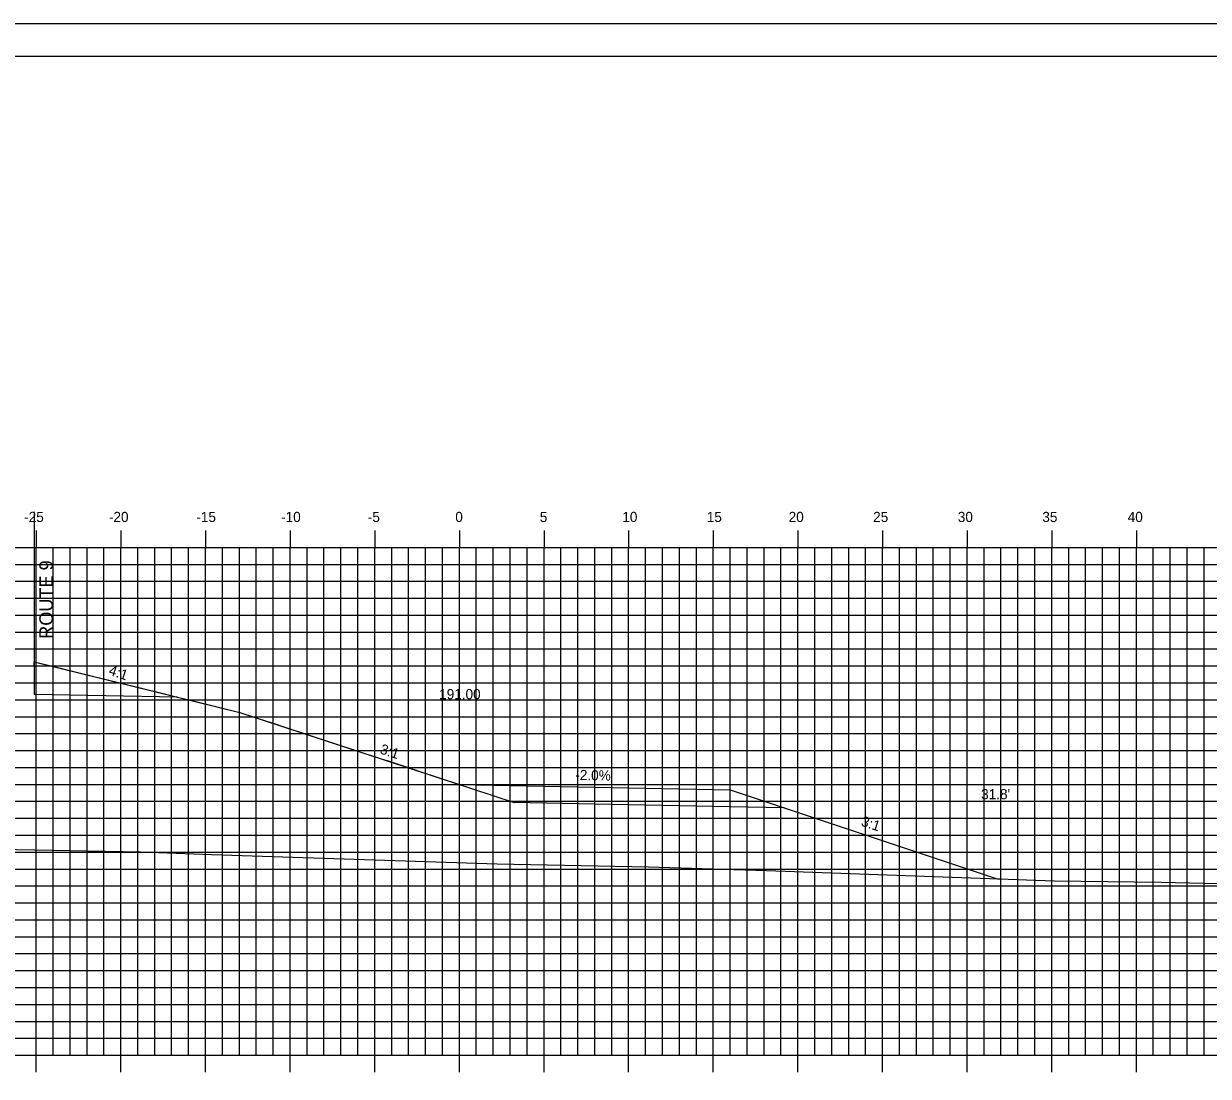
# Model space of a CAD drawing. Extents: x 1723961 to 1724133, y 459560 to 459670.
# Drawn here: x 1724018.7 to 1724088.7, y 459607.4 to 459669.6 of the extents above; entities that cross this region are included whole.
import ezdxf

# ---------------------------------------------------------------- set-up
doc = ezdxf.new("R2010")
doc.units = 0
for name, color, linetype in [('ANNOTATION', 7, 'Continuous'), ('BORDER', 7, 'Continuous'), ('D_Roadway_Centerline', 7, 'Continuous'), ('D_Roadway_Centerline_Text', 7, 'Continuous'), ('D_Roadway_Drive_Gravel', 7, 'Continuous'), ('D_Roadway_Edge_Shoulder', 7, 'Continuous'), ('D_Roadway_SlopeLines', 7, 'Continuous'), ('D_Roadway_SubGrade', 7, 'Continuous'), ('D_Text_Standard', 7, 'Continuous'), ('H_V ANNOTATION', 7, 'Continuous'), ('MAJOR', 7, 'Continuous'), ('MINOR', 7, 'Continuous'), ('PLOT BOUNDARY', 7, 'Continuous'), ('S_Roadway_Centerline', 7, 'Continuous')]:
    doc.layers.add(name, color=color, linetype=linetype)

msp = doc.modelspace()

# ---------------------------------------------------------------- linework, layer by layer
msp.add_lwpolyline([(1724044.473, 459624.613), (1724052.473, 459624.453), (1724060.473, 459624.293), (1724063.665, 459623.229), (1724076.243, 459619.036), (1724076.295, 459619.034), (1724076.313, 459619.033), (1724076.345, 459619.032), (1724076.366, 459619.032), (1724076.395, 459619.031), (1724076.417, 459619.03), (1724076.434, 459619.029)])
at = {"layer": 'BORDER'}
msp.add_lwpolyline([(1723969.473, 459562.613), (1724129.473, 459562.613), (1724129.473, 459667.613), (1723969.473, 459667.613)], close=True, dxfattribs=at)
at = {"layer": 'D_Roadway_Centerline'}
msp.add_lwpolyline([(1724019.359, 459631.855), (1724020.746, 459631.513), (1724022.556, 459631.068), (1724025.54, 459630.335), (1724026.973, 459629.982), (1724027.133, 459629.943), (1724027.825, 459629.773), (1724028.895, 459629.51), (1724031.508, 459628.867), (1724033.199, 459628.312), (1724033.218, 459628.306), (1724033.521, 459628.207), (1724034.108, 459628.014), (1724039.909, 459626.111), (1724040.2, 459626.015), (1724040.858, 459625.799), (1724043.086, 459625.068), (1724044.473, 459624.613)], dxfattribs=at)
at = {"layer": 'D_Roadway_Drive_Gravel'}
msp.add_lwpolyline([(1724044.474, 459624.613), (1724052.473, 459624.453), (1724060.473, 459624.293), (1724063.665, 459623.229), (1724060.473, 459623.293), (1724052.473, 459623.453), (1724047.719, 459623.548)], dxfattribs=at)
at = {"layer": 'D_Roadway_Edge_Shoulder'}
msp.add_line((1724019.359, 459631.855), (1724019.359, 459631.605), dxfattribs=at)
msp.add_line((1724019.359, 459631.855), (1724019.359, 459631.605), dxfattribs=at)
at = {"layer": 'D_Roadway_SlopeLines'}
for points in [[(1724019.359, 459631.855), (1724031.508, 459628.867), (1724047.719, 459623.548)], [(1724019.359, 459631.855), (1724031.508, 459628.867), (1724047.719, 459623.548)], [(1724019.359, 459631.855), (1724031.508, 459628.867), (1724047.719, 459623.548)], [(1724019.359, 459631.855), (1724031.508, 459628.867), (1724047.719, 459623.548)], [(1724019.359, 459631.855), (1724031.508, 459628.867), (1724047.719, 459623.548)], [(1724019.359, 459631.855), (1724031.508, 459628.867), (1724047.719, 459623.548)], [(1724019.359, 459631.855), (1724031.508, 459628.867), (1724044.474, 459624.613)], [(1724060.473, 459624.293), (1724063.665, 459623.229), (1724076.243, 459619.036)]]:
    msp.add_lwpolyline(points, dxfattribs=at)
at = {"layer": 'D_Roadway_SubGrade'}
msp.add_line((1724019.359, 459640.714), (1724019.359, 459629.931), dxfattribs=at)
msp.add_lwpolyline([(1724019.359, 459631.605), (1724019.359, 459631.855), (1724027.825, 459629.773), (1724019.359, 459629.931)], dxfattribs=at)
msp.add_lwpolyline([(1724019.359, 459631.605), (1724019.359, 459631.855), (1724027.825, 459629.773), (1724019.359, 459629.931)], dxfattribs=at)
at = {"layer": 'MAJOR'}
for p, q in [((1724019.473, 459639.615), (1724019.473, 459638.613)), ((1724024.473, 459639.615), (1724024.473, 459638.613)), ((1724029.473, 459639.615), (1724029.473, 459638.613)), ((1724034.473, 459639.615), (1724034.473, 459638.613)), ((1724039.473, 459639.615), (1724039.473, 459638.613)), ((1724044.473, 459639.615), (1724044.473, 459638.613)), ((1724049.473, 459639.615), (1724049.473, 459638.613)), ((1724054.473, 459639.615), (1724054.473, 459638.613)), ((1724059.473, 459639.615), (1724059.473, 459638.613)), ((1724064.473, 459639.615), (1724064.473, 459638.613)), ((1724069.473, 459639.615), (1724069.473, 459638.613)), ((1724074.473, 459639.615), (1724074.473, 459638.613)), ((1724079.473, 459639.615), (1724079.473, 459638.613)), ((1724084.473, 459639.615), (1724084.473, 459638.613)), ((1723974.473, 459638.613), (1724114.473, 459638.613)), ((1723974.473, 459638.613), (1724114.473, 459638.613)), ((1724019.473, 459608.613), (1724019.473, 459638.613)), ((1724024.473, 459608.613), (1724024.473, 459638.613)), ((1724029.473, 459608.613), (1724029.473, 459638.613)), ((1724034.473, 459608.613), (1724034.473, 459638.613)), ((1724039.473, 459608.613), (1724039.473, 459638.613)), ((1724044.473, 459608.613), (1724044.473, 459638.613)), ((1724049.473, 459608.613), (1724049.473, 459638.613)), ((1724054.473, 459608.613), (1724054.473, 459638.613)), ((1724059.473, 459608.613), (1724059.473, 459638.613)), ((1724064.473, 459608.613), (1724064.473, 459638.613)), ((1724069.473, 459608.613), (1724069.473, 459638.613)), ((1724074.473, 459608.613), (1724074.473, 459638.613)), ((1724079.473, 459608.613), (1724079.473, 459638.613)), ((1724084.473, 459608.613), (1724084.473, 459638.613)), ((1723974.473, 459633.613), (1724114.473, 459633.613)), ((1723974.473, 459628.613), (1724114.473, 459628.613)), ((1723974.473, 459623.613), (1724114.473, 459623.613)), ((1723974.473, 459618.613), (1724114.473, 459618.613)), ((1723974.473, 459613.613), (1724114.473, 459613.613)), ((1723974.473, 459608.613), (1724114.473, 459608.613)), ((1723974.473, 459608.613), (1724114.473, 459608.613)), ((1724019.473, 459607.611), (1724019.473, 459608.613)), ((1724024.473, 459607.611), (1724024.473, 459608.613)), ((1724029.473, 459607.611), (1724029.473, 459608.613)), ((1724034.473, 459607.611), (1724034.473, 459608.613)), ((1724039.473, 459607.611), (1724039.473, 459608.613)), ((1724044.473, 459607.611), (1724044.473, 459608.613)), ((1724049.473, 459607.611), (1724049.473, 459608.613)), ((1724054.473, 459607.611), (1724054.473, 459608.613)), ((1724059.473, 459607.611), (1724059.473, 459608.613)), ((1724064.473, 459607.611), (1724064.473, 459608.613)), ((1724069.473, 459607.611), (1724069.473, 459608.613)), ((1724074.473, 459607.611), (1724074.473, 459608.613)), ((1724079.473, 459607.611), (1724079.473, 459608.613)), ((1724084.473, 459607.611), (1724084.473, 459608.613))]:
    msp.add_line(p, q, dxfattribs=at)
at = {"layer": 'MINOR'}
for p, q in [((1724020.473, 459608.613), (1724020.473, 459638.613)), ((1724021.473, 459608.613), (1724021.473, 459638.613)), ((1724022.473, 459608.613), (1724022.473, 459638.613)), ((1724023.473, 459608.613), (1724023.473, 459638.613)), ((1724025.473, 459608.613), (1724025.473, 459638.613)), ((1724026.473, 459608.613), (1724026.473, 459638.613)), ((1724027.473, 459608.613), (1724027.473, 459638.613)), ((1724028.473, 459608.613), (1724028.473, 459638.613)), ((1724030.473, 459608.613), (1724030.473, 459638.613)), ((1724031.473, 459608.613), (1724031.473, 459638.613)), ((1724032.473, 459608.613), (1724032.473, 459638.613)), ((1724033.473, 459608.613), (1724033.473, 459638.613)), ((1724035.473, 459608.613), (1724035.473, 459638.613)), ((1724036.473, 459608.613), (1724036.473, 459638.613)), ((1724037.473, 459608.613), (1724037.473, 459638.613)), ((1724038.473, 459608.613), (1724038.473, 459638.613)), ((1724040.473, 459608.613), (1724040.473, 459638.613)), ((1724041.473, 459608.613), (1724041.473, 459638.613)), ((1724042.473, 459608.613), (1724042.473, 459638.613)), ((1724043.473, 459608.613), (1724043.473, 459638.613)), ((1724045.473, 459608.613), (1724045.473, 459638.613)), ((1724046.473, 459608.613), (1724046.473, 459638.613)), ((1724047.473, 459608.613), (1724047.473, 459638.613)), ((1724048.473, 459608.613), (1724048.473, 459638.613)), ((1724050.473, 459608.613), (1724050.473, 459638.613)), ((1724051.473, 459608.613), (1724051.473, 459638.613)), ((1724052.473, 459608.613), (1724052.473, 459638.613)), ((1724053.473, 459608.613), (1724053.473, 459638.613)), ((1724055.473, 459608.613), (1724055.473, 459638.613)), ((1724056.473, 459608.613), (1724056.473, 459638.613)), ((1724057.473, 459608.613), (1724057.473, 459638.613)), ((1724058.473, 459608.613), (1724058.473, 459638.613)), ((1724060.473, 459608.613), (1724060.473, 459638.613)), ((1724061.473, 459608.613), (1724061.473, 459638.613)), ((1724062.473, 459608.613), (1724062.473, 459638.613)), ((1724063.473, 459608.613), (1724063.473, 459638.613)), ((1724065.473, 459608.613), (1724065.473, 459638.613)), ((1724066.473, 459608.613), (1724066.473, 459638.613)), ((1724067.473, 459608.613), (1724067.473, 459638.613)), ((1724068.473, 459608.613), (1724068.473, 459638.613)), ((1724070.473, 459608.613), (1724070.473, 459638.613)), ((1724071.473, 459608.613), (1724071.473, 459638.613)), ((1724072.473, 459608.613), (1724072.473, 459638.613)), ((1724073.473, 459608.613), (1724073.473, 459638.613)), ((1724075.473, 459608.613), (1724075.473, 459638.613)), ((1724076.473, 459608.613), (1724076.473, 459638.613)), ((1724077.473, 459608.613), (1724077.473, 459638.613)), ((1724078.473, 459608.613), (1724078.473, 459638.613)), ((1724080.473, 459608.613), (1724080.473, 459638.613)), ((1724081.473, 459608.613), (1724081.473, 459638.613)), ((1724082.473, 459608.613), (1724082.473, 459638.613)), ((1724083.473, 459608.613), (1724083.473, 459638.613)), ((1724085.473, 459608.613), (1724085.473, 459638.613)), ((1724086.473, 459608.613), (1724086.473, 459638.613)), ((1724087.473, 459608.613), (1724087.473, 459638.613)), ((1724088.473, 459608.613), (1724088.473, 459638.613)), ((1723974.473, 459637.613), (1724114.473, 459637.613)), ((1723974.473, 459636.613), (1724114.473, 459636.613)), ((1723974.473, 459635.613), (1724114.473, 459635.613)), ((1723974.473, 459634.613), (1724114.473, 459634.613)), ((1723974.473, 459632.613), (1724114.473, 459632.613)), ((1723974.473, 459631.613), (1724114.473, 459631.613)), ((1723974.473, 459630.613), (1724114.473, 459630.613)), ((1723974.473, 459629.613), (1724114.473, 459629.613)), ((1723974.473, 459627.613), (1724114.473, 459627.613)), ((1723974.473, 459626.613), (1724114.473, 459626.613)), ((1723974.473, 459625.613), (1724114.473, 459625.613)), ((1723974.473, 459624.613), (1724114.473, 459624.613)), ((1723974.473, 459622.613), (1724114.473, 459622.613)), ((1723974.473, 459621.613), (1724114.473, 459621.613)), ((1723974.473, 459620.613), (1724114.473, 459620.613)), ((1723974.473, 459619.613), (1724114.473, 459619.613)), ((1723974.473, 459617.613), (1724114.473, 459617.613)), ((1723974.473, 459616.613), (1724114.473, 459616.613)), ((1723974.473, 459615.613), (1724114.473, 459615.613)), ((1723974.473, 459614.613), (1724114.473, 459614.613)), ((1723974.473, 459612.613), (1724114.473, 459612.613)), ((1723974.473, 459611.613), (1724114.473, 459611.613)), ((1723974.473, 459610.613), (1724114.473, 459610.613)), ((1723974.473, 459609.613), (1724114.473, 459609.613))]:
    msp.add_line(p, q, dxfattribs=at)
at = {"layer": 'PLOT BOUNDARY'}
msp.add_lwpolyline([(1723961.38, 459559.554), (1724131.38, 459559.554), (1724131.38, 459669.554), (1723961.38, 459669.554)], close=True, dxfattribs=at)
at = {"layer": 'S_Roadway_Centerline'}
msp.add_lwpolyline([(1723974.473, 459622.026), (1723980.836, 459621.977), (1723993.041, 459621.632), (1724003.846, 459620.758), (1724003.885, 459620.757), (1724016.201, 459620.797), (1724025.643, 459620.62), (1724029.818, 459620.462), (1724046.699, 459619.913), (1724055.648, 459619.732), (1724062.609, 459619.529), (1724079.625, 459618.914), (1724085.94, 459618.83), (1724091.007, 459618.726), (1724104.133, 459618.534), (1724113.511, 459618.184), (1724114.473, 459618.143)], dxfattribs=at)

# ---------------------------------------------------------------- texts
at = {"layer": 'ANNOTATION'}
for s, height, rotation, p in [('ROUTE 9', 0.8, 90, (1724020.456, 459633.213)), ('4:1', 0.6, 341.56505, (1724023.71, 459631.108)), ('3:1', 0.6, 341.56505, (1724039.739, 459626.454)), ('-2.0%', 0.6, 358.85424, (1724051.316, 459624.876)), ('3:1', 0.6, 341.56505, (1724068.16, 459622.185))]:
    msp.add_text(s, height=height, rotation=rotation, dxfattribs=at).set_placement(p)
at = {"layer": 'D_Roadway_Centerline_Text'}
msp.add_text('191.00', height=0.6, dxfattribs=at).set_placement((1724043.275, 459629.645))
at = {"layer": 'D_Text_Standard'}
msp.add_text("31.8'", height=0.6, dxfattribs=at).set_placement((1724075.299, 459623.736))
at = {"layer": 'H_V ANNOTATION'}
for s, p in [('-25', (1724018.759, 459640.113)), ('-20', (1724023.767, 459640.113)), ('-15', (1724028.93, 459640.113)), ('-10', (1724033.938, 459640.113)), ('-5', (1724039.064, 459640.113)), ('0', (1724044.232, 459640.113)), ('5', (1724049.224, 459640.113)), ('10', (1724054.098, 459640.113)), ('15', (1724059.09, 459640.113)), ('20', (1724063.927, 459640.113)), ('25', (1724068.919, 459640.113)), ('30', (1724073.922, 459640.113)), ('35', (1724078.914, 459640.113)), ('40', (1724083.959, 459640.113))]:
    msp.add_text(s, height=0.6, dxfattribs=at).set_placement(p)

doc.saveas('drawing.dxf')
